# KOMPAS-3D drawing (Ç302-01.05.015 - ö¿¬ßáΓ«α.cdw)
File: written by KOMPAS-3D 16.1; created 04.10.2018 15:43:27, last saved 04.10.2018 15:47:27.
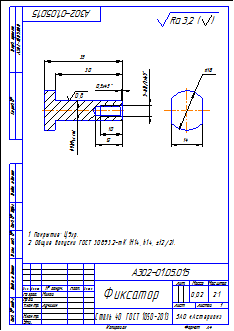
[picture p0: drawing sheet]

Sheet 1: A4, portrait

Title block, sheet 1: name: Фиксатор; designation: А302-01.05.015; material: Сталь 40  ГОСТ 1050-2013; mass: 0,02; scale: 2:1; sheets: 1; organisation: ЗАО «Астерион»; sheet format: A4; stored path: \\192.168.87.28\Konstructor_doc\Мембранные насосы\Мембранный электропривод\А302-00.00.000 - ASTRA-302 (МЭ200)\3Д ПВХ\А302-01.05.015 - Фиксатор.cdw; drawn by: Милов; technical control: Лучихин

Views: Вид 1, Местный разрез 1, Спереди, Проекционный вид 2, Проекционный вид 3
Referenced files in \\192.168.87.28\Konstructor_doc\Мембранные насосы\Мембранный электропривод\А302-00.00.000 - ASTRA-302 (МЭ200)\3Д ПВХ\: А302-01.05.015 - Фиксатор.m3d
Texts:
  Покрытие: Ц9хр.
  Общие допуски ГОСТ 30893.2-mK (H14, h14,  t2/2).
  Ra 3,2
  Ra 3,2 ( )
Dimensions and other numbers on the sheet: 30; 35; 9; -6Н/1 45; 5; 10; 12; 0,5; 0,8; 14; 18; 2:1; 1; 0,02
